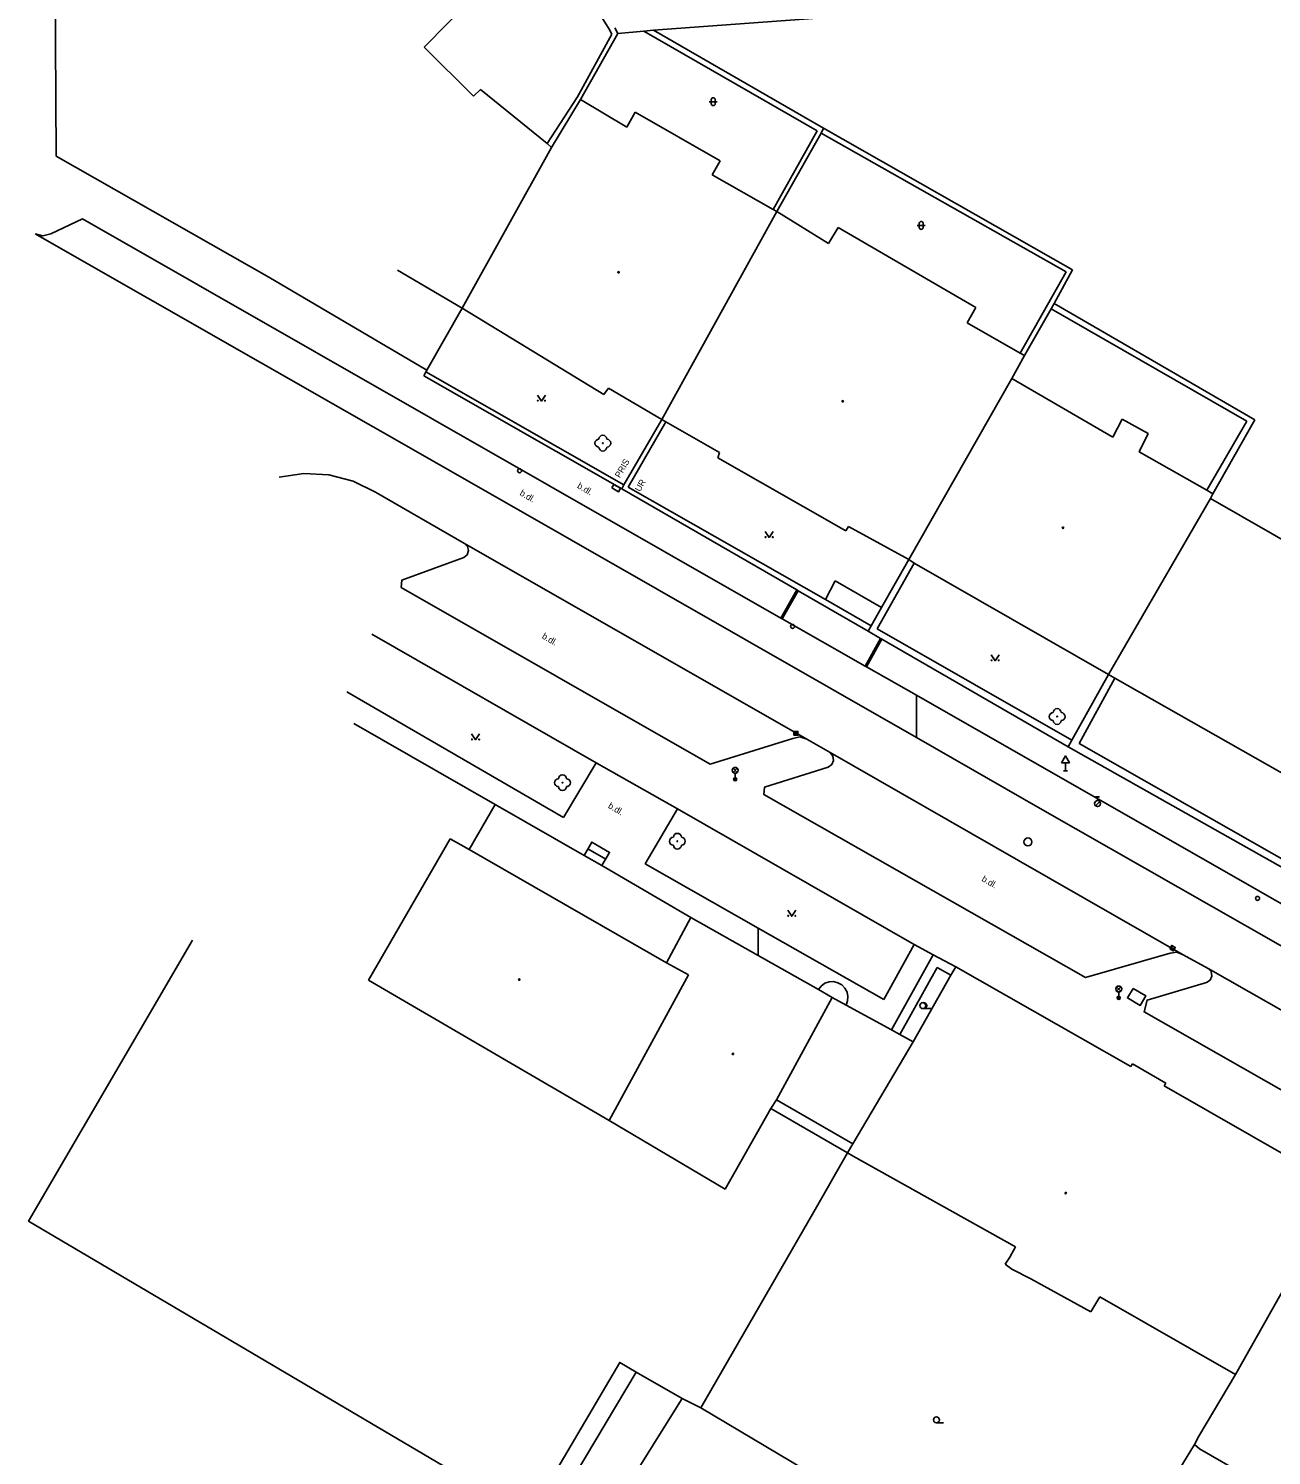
# Model space of a CAD drawing. Extents: x -599770 to -598493, y -1162076 to -1159209.
# Drawn here: x -599197.2 to -599118.7, y -1159605.2 to -1159515 of the extents above; entities that cross this region are included whole.
import ezdxf

# ---------------------------------------------------------------- set-up
doc = ezdxf.new("R2010")
doc.units = 0
doc.layers.add('Podklad', color=7, linetype='Continuous')

msp = doc.modelspace()

# ---------------------------------------------------------------- linework, layer by layer
at = {"layer": 'Podklad'}
for p, q in [((-599154.173, -1159519.648), (-599153.673, -1159519.648)), ((-599154.048, -1159519.523), (-599154.048, -1159519.773)), ((-599153.798, -1159519.523), (-599153.798, -1159519.773)), ((-599141.033, -1159527.468), (-599140.533, -1159527.468)), ((-599140.908, -1159527.343), (-599140.908, -1159527.593)), ((-599140.658, -1159527.343), (-599140.658, -1159527.593)), ((-599148.825, -1159559.57), (-599148.575, -1159559.57)), ((-599131.67, -1159561.431), (-599131.67, -1159561.94)), ((-599152.672, -1159562.04), (-599152.407, -1159561.775)), ((-599152.672, -1159561.775), (-599152.407, -1159562.04)), ((-599152.54, -1159562.095), (-599152.54, -1159562.47)), ((-599131.795, -1159561.94), (-599131.545, -1159561.94)), ((-599129.769, -1159564.146), (-599129.504, -1159563.881)), ((-599129.765, -1159563.573), (-599129.515, -1159563.573)), ((-599129.64, -1159563.823), (-599129.64, -1159563.573)), ((-599125.008, -1159573.088), (-599124.792, -1159573.212)), ((-599128.433, -1159575.86), (-599128.168, -1159575.595)), ((-599128.433, -1159575.595), (-599128.168, -1159575.86)), ((-599128.3, -1159575.915), (-599128.3, -1159576.29)), ((-599140.68, -1159576.968), (-599140.18, -1159576.968)), ((-599139.82, -1159603.148), (-599139.383, -1159603.148))]:
    msp.add_line(p, q, dxfattribs=at)
for points in [[(-599172.02, -1159536.62), (-599182, -1159530.74), (-599195.45, -1159523.09), (-599195.52, -1159508.54), (-599181.24, -1159500.16)], [(-599164.58, -1159508.47), (-599172.2, -1159516.2)], [(-599164.58, -1159508.47), (-599160.5, -1159515.07)], [(-599157.69, -1159515.12), (-599142.16, -1159513.99)], [(-599160.33, -1159515.38), (-599162.5, -1159519.34)], [(-599162.31, -1159519.51), (-599159.95, -1159515.33)], [(-599160.5, -1159515.07), (-599160.33, -1159515.38)], [(-599160.15, -1159514.98), (-599159.95, -1159515.33)], [(-599159.95, -1159515.33), (-599158.32, -1159515.19)], [(-599158.32, -1159515.19), (-599157.69, -1159515.12)], [(-599158.32, -1159515.19), (-599147.35, -1159521.49)], [(-599146.95, -1159521.32), (-599157.69, -1159515.12)], [(-599172.2, -1159516.2), (-599169.07, -1159519.29)], [(-599169.07, -1159519.29), (-599168.64, -1159518.87)], [(-599168.64, -1159518.87), (-599164.42, -1159522.29)], [(-599162.5, -1159519.34), (-599164.42, -1159522.29)], [(-599164.15, -1159522.55), (-599162.31, -1159519.51)], [(-599162.31, -1159519.51), (-599159.38, -1159521.25)], [(-599159.38, -1159521.25), (-599158.86, -1159520.31)], [(-599158.86, -1159520.31), (-599153.49, -1159523.38)], [(-599147.35, -1159521.49), (-599150.13, -1159526.47)], [(-599149.9, -1159526.59), (-599147.1, -1159521.64)], [(-599147.1, -1159521.64), (-599146.95, -1159521.32)], [(-599147.1, -1159521.64), (-599131.63, -1159530.4)], [(-599131.23, -1159530.28), (-599146.95, -1159521.32)], [(-599169.78, -1159532.7), (-599164.15, -1159522.55)], [(-599164.42, -1159522.29), (-599164.15, -1159522.55)], [(-599153.49, -1159523.38), (-599153.99, -1159524.28)], [(-599153.99, -1159524.28), (-599150.13, -1159526.47)], [(-599150.13, -1159526.47), (-599149.9, -1159526.59)], [(-599149.66, -1159552.29), (-599193.77, -1159527.06), (-599195.79, -1159528.01), (-599196.28, -1159528.13), (-599196.77, -1159528.01)], [(-599157.18, -1159539.74), (-599149.9, -1159526.59)], [(-599149.9, -1159526.59), (-599146.64, -1159528.61)], [(-599196.77, -1159528.01), (-599168.3, -1159544.27), (-599141.084, -1159559.839), (-599133.11, -1159564.4), (-599107.4, -1159579.07), (-599098.775, -1159583.988), (-599081.69, -1159593.73)], [(-599146.64, -1159528.61), (-599146.02, -1159527.6)], [(-599146.02, -1159527.6), (-599137.32, -1159532.65)], [(-599169.78, -1159532.7), (-599173.88, -1159530.29)], [(-599131.63, -1159530.4), (-599134.52, -1159535.54)], [(-599132.39, -1159532.4), (-599131.23, -1159530.28)], [(-599172.02, -1159536.62), (-599169.78, -1159532.7)], [(-599160.83, -1159538.16), (-599169.78, -1159532.7)], [(-599137.32, -1159532.65), (-599137.87, -1159533.63)], [(-599134.26, -1159535.68), (-599132.57, -1159532.75)], [(-599132.57, -1159532.75), (-599132.39, -1159532.4)], [(-599132.57, -1159532.75), (-599120.21, -1159539.85)], [(-599119.7, -1159539.76), (-599132.39, -1159532.4)], [(-599137.87, -1159533.63), (-599134.52, -1159535.54)], [(-599134.52, -1159535.54), (-599134.26, -1159535.68)], [(-599134.26, -1159535.68), (-599135.05, -1159537.14)], [(-599172.22, -1159536.97), (-599172.08, -1159536.72)], [(-599172.22, -1159536.97), (-599159.71, -1159544.11)], [(-599172.08, -1159536.72), (-599172.02, -1159536.62)], [(-599159.57, -1159543.87), (-599172.08, -1159536.72)], [(-599141.56, -1159548.59), (-599135.05, -1159537.14)], [(-599135.05, -1159537.14), (-599128.67, -1159540.86)], [(-599165.03, -1159538.195), (-599164.78, -1159538.57), (-599164.53, -1159538.195)], [(-599160.55, -1159537.76), (-599160.83, -1159538.16)], [(-599157.18, -1159539.74), (-599160.55, -1159537.76)], [(-599159.57, -1159543.87), (-599157.18, -1159539.74)], [(-599159.3, -1159544.01), (-599156.92, -1159539.89)], [(-599156.92, -1159539.89), (-599157.18, -1159539.74)], [(-599153.53, -1159541.81), (-599156.92, -1159539.89)], [(-599128.67, -1159540.86), (-599128.08, -1159539.71)], [(-599128.08, -1159539.71), (-599126.44, -1159540.63)], [(-599120.21, -1159539.85), (-599122.74, -1159544.2)], [(-599122.36, -1159544.44), (-599119.7, -1159539.76)], [(-599126.44, -1159540.63), (-599127, -1159541.77)], [(-599153.63, -1159542.15), (-599153.53, -1159541.81)], [(-599127, -1159541.77), (-599122.74, -1159544.2)], [(-599145.54, -1159546.78), (-599153.63, -1159542.15)], [(-599181.35, -1159543.37), (-599179.79, -1159543.14), (-599178.21, -1159543.23), (-599176.68, -1159543.63), (-599175.26, -1159544.33), (-599169.65, -1159547.57)], [(-599159.71, -1159544.11), (-599159.57, -1159543.87)], [(-599159.71, -1159544.11), (-599148.64, -1159550.51)], [(-599146.83, -1159551.12), (-599159.3, -1159544.01)], [(-599122.74, -1159544.2), (-599122.36, -1159544.44)], [(-599122.36, -1159544.44), (-599122.51, -1159544.72)], [(-599128.94, -1159555.85), (-599122.51, -1159544.72)], [(-599122.51, -1159544.72), (-599106.91, -1159553.65)], [(-599150.64, -1159546.815), (-599150.39, -1159547.19), (-599150.14, -1159546.815)], [(-599145.38, -1159546.5), (-599145.54, -1159546.78)], [(-599141.56, -1159548.59), (-599145.38, -1159546.5)], [(-599169.65, -1159547.57), (-599169.45, -1159547.76), (-599169.38, -1159548.02), (-599169.47, -1159548.29), (-599169.68, -1159548.46), (-599173.61, -1159549.89), (-599173.64, -1159550.36)], [(-599148.02, -1159559.94), (-599169.65, -1159547.57)], [(-599143.57, -1159552.97), (-599141.22, -1159548.82)], [(-599143.3, -1159551.62), (-599141.56, -1159548.59)], [(-599141.22, -1159548.82), (-599141.56, -1159548.59)], [(-599128.94, -1159555.85), (-599141.22, -1159548.82)], [(-599146.22, -1159549.94), (-599146.83, -1159551.12)], [(-599143.3, -1159551.62), (-599146.22, -1159549.94)], [(-599173.64, -1159550.36), (-599154.11, -1159561.51), (-599148.89, -1159559.89), (-599148.46, -1159559.8), (-599148.02, -1159559.94)], [(-599148.64, -1159550.51), (-599149.66, -1159552.29)], [(-599148.56, -1159550.56), (-599149.57, -1159552.34)], [(-599148.64, -1159550.51), (-599148.56, -1159550.56)], [(-599148.56, -1159550.56), (-599144.13, -1159553.12)], [(-599143.94, -1159552.78), (-599146.83, -1159551.12)], [(-599143.94, -1159552.78), (-599143.3, -1159551.62)], [(-599149.57, -1159552.34), (-599149.66, -1159552.29)], [(-599144.33, -1159555.32), (-599149.57, -1159552.34)], [(-599161.33, -1159561.43), (-599175.49, -1159553.3)], [(-599143.35, -1159553.57), (-599144.33, -1159555.32)], [(-599143.26, -1159553.62), (-599144.24, -1159555.36)], [(-599144.13, -1159553.12), (-599143.94, -1159552.78)], [(-599144.13, -1159553.12), (-599143.35, -1159553.57)], [(-599131.26, -1159560.01), (-599143.57, -1159552.97)], [(-599143.35, -1159553.57), (-599143.26, -1159553.62)], [(-599143.26, -1159553.62), (-599131.5, -1159560.43)], [(-599144.24, -1159555.36), (-599144.33, -1159555.32)], [(-599089.13, -1159586.86), (-599097.662, -1159581.983), (-599141.089, -1159557.161), (-599144.24, -1159555.36)], [(-599136.36, -1159554.605), (-599136.11, -1159554.98), (-599135.86, -1159554.605)], [(-599131.26, -1159560.01), (-599128.94, -1159555.85)], [(-599130.81, -1159560.21), (-599128.55, -1159556.08)], [(-599128.55, -1159556.08), (-599128.94, -1159555.85)], [(-599113.29, -1159564.75), (-599128.55, -1159556.08)], [(-599163.38, -1159564.89), (-599177.07, -1159556.94)], [(-599141.084, -1159559.839), (-599141.089, -1159557.161)], [(-599176.63, -1159558.94), (-599167.71, -1159564.06)], [(-599169.19, -1159559.605), (-599168.94, -1159559.98), (-599168.69, -1159559.605)], [(-599148.02, -1159559.94), (-599146.53, -1159560.79)], [(-599146.53, -1159560.79), (-599146.36, -1159561.01), (-599146.33, -1159561.28), (-599146.44, -1159561.54), (-599146.66, -1159561.7), (-599150.69, -1159562.98), (-599150.72, -1159563.44), (-599130.41, -1159575.01), (-599125.06, -1159573.47), (-599124.63, -1159573.4), (-599124.22, -1159573.56)], [(-599124.22, -1159573.56), (-599134.64, -1159567.61), (-599146.53, -1159560.79)], [(-599131.5, -1159560.43), (-599131.26, -1159560.01)], [(-599131.5, -1159560.43), (-599107.85, -1159573.76)], [(-599107.68, -1159573.39), (-599130.81, -1159560.21)], [(-599161.33, -1159561.43), (-599163.38, -1159564.89)], [(-599156.19, -1159564.35), (-599161.33, -1159561.43)], [(-599167.71, -1159564.06), (-599169.35, -1159566.92)], [(-599167.71, -1159564.06), (-599162.08, -1159567.29)], [(-599158.23, -1159567.82), (-599156.19, -1159564.35)], [(-599141.22, -1159572.91), (-599156.19, -1159564.35)], [(-599175.71, -1159575.17), (-599170.55, -1159566.23)], [(-599170.55, -1159566.23), (-599169.35, -1159566.92)], [(-599169.35, -1159566.92), (-599156.88, -1159574.08)], [(-599162.08, -1159567.29), (-599161.6, -1159566.44), (-599160.47, -1159567.1), (-599160.96, -1159567.92)], [(-599161.84, -1159566.87), (-599160.72, -1159567.52)], [(-599162.08, -1159567.29), (-599160.96, -1159567.92)], [(-599160.96, -1159567.92), (-599155.33, -1159571.2)], [(-599143.14, -1159576.39), (-599151.091, -1159571.874), (-599158.23, -1159567.82)], [(-599149.21, -1159570.755), (-599148.96, -1159571.13), (-599148.71, -1159570.755)], [(-599156.88, -1159574.08), (-599155.33, -1159571.2)], [(-599155.33, -1159571.2), (-599151.088, -1159573.606), (-599147.278, -1159575.768), (-599146.41, -1159576.26)], [(-599151.088, -1159573.606), (-599151.091, -1159571.874)], [(-599158.8, -1159599.94), (-599159.83, -1159599.33), (-599165.55, -1159609.06), (-599197.19, -1159590.4), (-599186.84, -1159572.64)], [(-599141.22, -1159572.91), (-599143.14, -1159576.39)], [(-599140.02, -1159573.57), (-599141.22, -1159572.91)], [(-599155.48, -1159574.84), (-599156.88, -1159574.08)], [(-599140.02, -1159573.57), (-599142.66, -1159578.31)], [(-599142.13, -1159578.6), (-599139.78, -1159574.38)], [(-599138.6, -1159574.33), (-599140.02, -1159573.57)], [(-599139.78, -1159574.38), (-599138.9, -1159574.85)], [(-599138.9, -1159574.85), (-599138.6, -1159574.33)], [(-599138.6, -1159574.33), (-599127.53, -1159580.63)], [(-599124.22, -1159573.56), (-599122.65, -1159574.43)], [(-599160.49, -1159584.05), (-599175.71, -1159575.17)], [(-599160.49, -1159584.05), (-599155.48, -1159574.84)], [(-599145.53, -1159576.741), (-599145.43, -1159576.48), (-599145.41, -1159576.2), (-599145.47, -1159575.92), (-599145.6, -1159575.67), (-599145.8, -1159575.47), (-599146.05, -1159575.33), (-599146.32, -1159575.26), (-599146.6, -1159575.28), (-599146.87, -1159575.37), (-599147.1, -1159575.54), (-599147.278, -1159575.768)], [(-599141.28, -1159579.06), (-599138.9, -1159574.85)], [(-599122.65, -1159574.43), (-599122.46, -1159574.63), (-599122.41, -1159574.91), (-599122.52, -1159575.16), (-599122.75, -1159575.32), (-599126.5, -1159576.43), (-599126.7, -1159577.18), (-599109.71, -1159586.85), (-599104.45, -1159585.21), (-599104.01, -1159585.16), (-599103.59, -1159585.28)], [(-599103.59, -1159585.28), (-599122.65, -1159574.43)], [(-599127.39, -1159575.69), (-599126.58, -1159576.17), (-599126.94, -1159576.77), (-599127.75, -1159576.29), (-599127.39, -1159575.69)], [(-599146.41, -1159576.26), (-599149.93, -1159582.73)], [(-599146.41, -1159576.26), (-599145.53, -1159576.741), (-599142.66, -1159578.31)], [(-599142.66, -1159578.31), (-599142.13, -1159578.6)], [(-599141.28, -1159579.06), (-599142.13, -1159578.6)], [(-599145.1, -1159585.52), (-599141.28, -1159579.06)], [(-599127.53, -1159580.63), (-599127.44, -1159580.45)], [(-599127.44, -1159580.45), (-599125.33, -1159581.68)], [(-599125.33, -1159581.68), (-599125.42, -1159581.84)], [(-599125.42, -1159581.84), (-599114.25, -1159588.26)], [(-599150.29, -1159583.29), (-599153.17, -1159588.37)], [(-599149.93, -1159582.73), (-599150.29, -1159583.29)], [(-599145.43, -1159586.09), (-599150.29, -1159583.29)], [(-599149.93, -1159582.73), (-599145.1, -1159585.52)], [(-599153.17, -1159588.37), (-599160.49, -1159584.05)], [(-599154.7, -1159602.21), (-599147.57, -1159589.82), (-599145.43, -1159586.09)], [(-599145.43, -1159586.09), (-599145.1, -1159585.52)], [(-599145.08, -1159586.3), (-599145.43, -1159586.09)], [(-599134.83, -1159592.02), (-599145.08, -1159586.3)], [(-599114.25, -1159588.26), (-599120.92, -1159600.09)], [(-599135.19, -1159592.67), (-599134.83, -1159592.02)], [(-599135.47, -1159593.12), (-599135.19, -1159592.67)], [(-599135.06, -1159593.44), (-599135.47, -1159593.12)], [(-599133.85, -1159594.05), (-599135.06, -1159593.44)], [(-599130.07, -1159596.13), (-599133.85, -1159594.05)], [(-599129.5, -1159595.18), (-599130.07, -1159596.13)], [(-599120.92, -1159600.09), (-599129.5, -1159595.18)], [(-599167.23, -1159614.09), (-599158.8, -1159599.94)], [(-599158.8, -1159599.94), (-599155.88, -1159601.6)], [(-599123.24, -1159604), (-599120.92, -1159600.09)], [(-599155.88, -1159601.6), (-599162.562, -1159612.281), (-599164.47, -1159615.33)], [(-599154.7, -1159602.21), (-599155.88, -1159601.6)], [(-599130.79, -1159616.42), (-599146.483, -1159607.093), (-599154.7, -1159602.21)], [(-599123.52, -1159604.51), (-599123.24, -1159604)], [(-599123.52, -1159604.51), (-599130.79, -1159616.42)], [(-599123.19, -1159604.8), (-599123.52, -1159604.51)], [(-599118.88, -1159607.28), (-599123.19, -1159604.8)]]:
    msp.add_lwpolyline(points, dxfattribs=at)
for points in [[(-599160.339, -1159544.055), (-599159.905, -1159544.302), (-599159.781, -1159544.085), (-599160.215, -1159543.838)], [(-599148.825, -1159559.695), (-599148.575, -1159559.695), (-599148.575, -1159559.445), (-599148.825, -1159559.445)], [(-599131.92, -1159561.431), (-599131.42, -1159561.431), (-599131.67, -1159560.998)], [(-599125.071, -1159573.196), (-599124.854, -1159573.321), (-599124.729, -1159573.104), (-599124.946, -1159572.979)]]:
    msp.add_lwpolyline(points, close=True, dxfattribs=at)
for centre, radius in [((-599159.91, -1159530.43), 0.045), ((-599159.91, -1159530.43), 0.0199), ((-599165.005, -1159538.545), 0.025), ((-599164.555, -1159538.545), 0.025), ((-599145.74, -1159538.58), 0.045), ((-599145.74, -1159538.58), 0.0199), ((-599160.9, -1159541.23), 0.025), ((-599166.16, -1159542.97), 0.125), ((-599150.615, -1159547.165), 0.025), ((-599150.165, -1159547.165), 0.025), ((-599131.82, -1159546.58), 0.045), ((-599131.82, -1159546.58), 0.0199), ((-599148.91, -1159552.81), 0.125), ((-599136.335, -1159554.955), 0.025), ((-599135.885, -1159554.955), 0.025), ((-599132.19, -1159558.51), 0.025), ((-599169.165, -1159559.955), 0.025), ((-599168.715, -1159559.955), 0.025), ((-599152.54, -1159561.907), 0.188), ((-599152.54, -1159562.47), 0.1), ((-599152.54, -1159562.47), 0.0723), ((-599152.54, -1159562.47), 0.0438), ((-599163.45, -1159562.69), 0.025), ((-599129.64, -1159564.01), 0.188), ((-599134.04, -1159566.43), 0.25), ((-599156.19, -1159566.39), 0.025), ((-599119.53, -1159570), 0.125), ((-599149.185, -1159571.105), 0.025), ((-599148.735, -1159571.105), 0.025), ((-599166.18, -1159575.13), 0.045), ((-599166.18, -1159575.13), 0.0199), ((-599128.3, -1159575.727), 0.188), ((-599140.68, -1159576.78), 0.188), ((-599128.3, -1159576.29), 0.1), ((-599128.3, -1159576.29), 0.0723), ((-599128.3, -1159576.29), 0.0438), ((-599152.68, -1159579.83), 0.045), ((-599152.68, -1159579.83), 0.0199), ((-599131.65, -1159588.63), 0.045), ((-599131.65, -1159588.63), 0.0199), ((-599139.82, -1159602.96), 0.188)]:
    msp.add_circle(centre, radius, dxfattribs=at)
for centre, radius, start, end in [((-599153.923, -1159519.523), 0.125, 0, 180), ((-599153.923, -1159519.773), 0.125, 180, 0), ((-599140.783, -1159527.343), 0.125, 0, 180), ((-599140.783, -1159527.593), 0.125, 180, 0), ((-599161.15, -1159541.23), 0.25, 90, 270), ((-599160.9, -1159540.98), 0.25, 0, 180), ((-599160.65, -1159541.23), 0.25, 270, 90), ((-599160.9, -1159541.48), 0.25, 180, 0), ((-599132.19, -1159558.26), 0.25, 0, 180), ((-599132.44, -1159558.51), 0.25, 90, 270), ((-599132.19, -1159558.76), 0.25, 180, 0), ((-599131.94, -1159558.51), 0.25, 270, 90), ((-599163.7, -1159562.69), 0.25, 90, 270), ((-599163.45, -1159562.44), 0.25, 0, 180), ((-599163.2, -1159562.69), 0.25, 270, 90), ((-599163.45, -1159562.94), 0.25, 180, 0), ((-599156.44, -1159566.39), 0.25, 90, 270), ((-599156.19, -1159566.14), 0.25, 0, 180), ((-599155.94, -1159566.39), 0.25, 270, 90), ((-599156.19, -1159566.64), 0.25, 180, 0), ((-599140.617, -1159576.78), 0.188, 260.40593, 99.59407)]:
    msp.add_arc(centre, radius, start, end, dxfattribs=at)

# ---------------------------------------------------------------- texts
for s, rotation, p in [('PRIS', 59.98, (-599159.82, -1159543.46)), ('b.dl.', 329.62, (-599162.56, -1159544.04)), ('UR', 60.23, (-599158.55, -1159544.33)), ('b.dl.', 329.62, (-599166.19, -1159544.49)), ('b.dl.', 329.62, (-599164.79, -1159553.54)), ('b.dl.', 329.62, (-599160.61, -1159564.26)), ('b.dl.', 329.62, (-599137, -1159568.88))]:
    msp.add_text(s, height=0.4, rotation=rotation, dxfattribs=at).set_placement(p)

doc.saveas('drawing.dxf')
